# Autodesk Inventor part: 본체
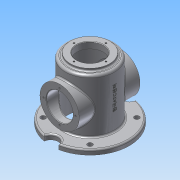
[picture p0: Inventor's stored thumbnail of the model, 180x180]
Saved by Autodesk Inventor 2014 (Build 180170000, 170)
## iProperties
Created: 2018-04
Part Number: 본체
Material: 알루미늄 6061
Document SubType Name: Modeling
Designer: user
Density: 2.71 g/cm^3
Appearance: 알루미늄 - 평지
Mass: 1151.48 g
Surface Area: 1200.97 cm^2
Volume: 424.901 cm^3
Author: user
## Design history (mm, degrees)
sketch "스케치1"
  geometry: C1 r 50 at (0, 0); 1 further point
  constraints: 1 centre point, 1 coincident
  dimensions: "d0" = 100 diameter of C1
extrude "돌출1" new body sketch "스케치1" distance "d1" = 128; taper "d2" = 0 deg
sketch "스케치2"
  geometry: C1 r 50 at (0, 0) reference; C2 r 40 at (0, 0)
  constraints: 1 centre point, 1 coincident
  dimensions: "d3" = 80 diameter of C2
extrude "돌출2" join sketch "스케치2" distance "d4" = 5; taper "d5" = 0 deg
node "작업 평면1"
sketch "스케치3"
  geometry: C1 r 80 at (0, 0); 1 further point
  constraints: 1 centre point, 1 coincident
  dimensions: "d7" = 160 diameter of C1
extrude "돌출3" join sketch "스케치3" distance "d8" = 10; taper "d9" = 0 deg
sketch "스케치4"
  geometry: C1 r 40 at (0, 0) reference; C2 r 27 at (0, 0)
  constraints: 1 centre point, 1 coincident
  dimensions: "d10" = 54 diameter of C2
extrude "돌출4" cut sketch "스케치4" stored distance "d11" = 10; taper "d12" = 0 deg
sketch "스케치5"
  geometry: C1 r 27 at (0, 0) reference; C2 r 50 at (0, 0) reference; C3 r 45 at (0, 0)
  constraints: 1 centre point, 1 coincident
  dimensions: "d13" = 90 diameter of C3
extrude "돌출5" cut sketch "스케치5" distance "d14" = 120; taper "d15" = 0 deg
node "작업 평면2"
sketch "스케치6"
  geometry: L1 (-80, 8)-(80, 8) reference; C1 r 40 at (0, 68); 1 further point
  constraints: 1 centre point, 1 vertical alignment
  dimensions: "d17" = 80 diameter of C1; "d18" = 60 distance from line of C1.centre L1
extrude "돌출6" join sketch "스케치6" distance "d19" = 124; taper "d20" = 0 deg
sketch "스케치7"
  geometry: C1 r 40 at (0, 0) reference; C2 r 27 at (0, 0); 1 further point
  constraints: 1 centre point, 1 coincident
  dimensions: "d21" = 54 diameter of C2
extrude "돌출7" cut sketch "스케치7" stored distance "d22" = 124; taper "d23" = 0 deg
sketch "스케치8"
  geometry: C1 r 15 at (0, -80); C2 r 15 at (0, 80); C3 r 80 at (0, 0) reference; A1 r 80 centre (0, 0) between (0, -80) and (0, 80) reference
  constraints: 2 centre point, 2 point on circle, 2 vertical alignment
  dimensions: "d24" = 30 diameter of C1; "d25" = 30 diameter of C2
extrude "돌출8" cut sketch "스케치8" distance "d26" = 124; taper "d27" = 0 deg
sketch "스케치9" dims "d30" = 135
  geometry: L1 (0, 0)-(-80, 0); L2 (0, 0)-(-56.569, -56.569); L3 (0, 0)-(-56.569, 56.569); L4 (0, 0)-(56.569, -56.569); L5 (0, 0)-(56.569, 56.569); L6 (0, 0)-(-56.569, 56.569); C1 r 45 at (0, 0) reference; C2 r 50 at (0, 0) reference; C3 r 5 at (-47.73, -47.73); C4 r 5 at (47.73, -47.73); C5 r 5 at (47.73, 47.73); C6 r 5 at (-47.73, 47.73); A1 r 80 centre (0, 0) between (-14.934, 78.594) and (-14.934, -78.594) reference; A2 r 15 centre (0, -80) between (14.934, -78.594) and (-14.934, -78.594) reference; A3 r 80 centre (0, 0) between (-14.934, 78.594) and (-14.934, -78.594) reference; A4 r 15 centre (0, 80) between (-14.934, 78.594) and (14.934, 78.594) reference; A5 r 80 centre (0, 0) between (14.934, -78.594) and (14.934, 78.594) reference; 1 further point
  constraints: 12 end point, 5 point on circle, 4 centre point, 4 point on line, 1 coincident, 24 other
  dimensions: "d28" = 45 deg angle of L1 L2; "d29" = 90 deg angle of L3 L2; "d31" = 10 diameter of C3; "d34" = 360 deg dimension on A1.centre L2.end (derived)
extrude "돌출9" cut sketch "스케치9" distance "d36" = 124; taper "d37" = 0 deg
node "작업 평면3"
sketch "스케치10"
  geometry: L1 (-78.594, 8)-(78.594, 8) reference; 2 further points
  constraints: 1 vertical alignment, 1 other
  dimensions: "d79" = 70 distance from line of L1 point (0, 78)
feature "엠보싱1" sketch "스케치10" dims "d40" = 0.5, "d41" = 0
sketch "스케치11" dims "d42" = 65
  geometry: C1 r 27 at (0, 0) reference; C2 r 40 at (0, 0) reference; 5 further points
  constraints: 2 horizontal alignment, 1 coincident, 7 other
  dimensions: "d45" = 360 deg dimension on C1.centre point (-32.5, 0) (derived)
hole "구멍1" sketch "스케치11" at (-32.5, 0), (0, -32.5), (32.5, 0), (0, 32.5) diameter "d47" = 3.242; stored, may be unused: countersink angle "d51" = 90 deg, drill point angle "d53" = 118 deg; dims "d48" = 8, "d49" = 4, "d50" = 2, "d52" = 10
sketch "스케치12" dims "d54" = 65
  geometry: C1 r 27 at (0, 0) reference; C2 r 40 at (0, 0) reference; 6 further points
  constraints: 2 vertical alignment, 1 coincident, 7 other
  dimensions: "d57" = 360 deg dimension on C1.centre point (0, 32.5) (derived)
hole "구멍2" sketch "스케치12" at (0, 32.5), (-32.5, 0), (0, -32.5), (32.5, 0) diameter "d59" = 3.242; stored, may be unused: countersink angle "d63" = 90 deg, drill point angle "d65" = 118 deg; dims "d60" = 8, "d61" = 4, "d62" = 2, "d64" = 10
fillet "모깎기1" dims "d66" = 5
fillet "모깎기2" dims "d67" = 3
chamfer "모따기1" distance "d68" = 1; stored, may be unused: second distance "d69" = 2, angle "d70" = 45 deg
fillet "모깎기3" dims "d71" = 3
sketch "스케치13"
  geometry: C1 r 45 at (0, 0) reference; C2 r 50 at (0, 0) reference; C3 r 45 at (0, 0)
  constraints: 1 centre point, 1 coincident
  dimensions: "d72" = 90 diameter of C3
extrude "돌출10" cut sketch "스케치13" distance "d73" = 115; taper "d74" = 0 deg
chamfer "모따기2" distance "d75" = 1; stored, may be unused: second distance "d76" = 2, angle "d77" = 45 deg
fillet "모깎기4" dims "d78" = 3
node "솔리드1"
mirror "대칭1"
node "절단 모서리 투영1"
other parameters: "d6" = 8, "d16" = 62
